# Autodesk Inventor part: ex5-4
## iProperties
Shininess: 64.0
Length Units: 11272
Angle Units: 11279
Time Units: 11290
Mass Units: 11286
Length Display Precision: 3
Angle Display Precision: 2
Compacted: True
Part Number: ex5-4
Document SubType Name: Modeling
Created: 2002-09
Designer: Elise Moss
Density: 0.0
Volumn: 0.0
Area: 0.0
PropertySet Name: Model Information
Control State: 0
Master: False
Checked Out: False
Author: Elise Moss
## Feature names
1. Revolution1
2. Hole1
3. Shell1
